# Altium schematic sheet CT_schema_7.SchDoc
size 274 x 160 mm
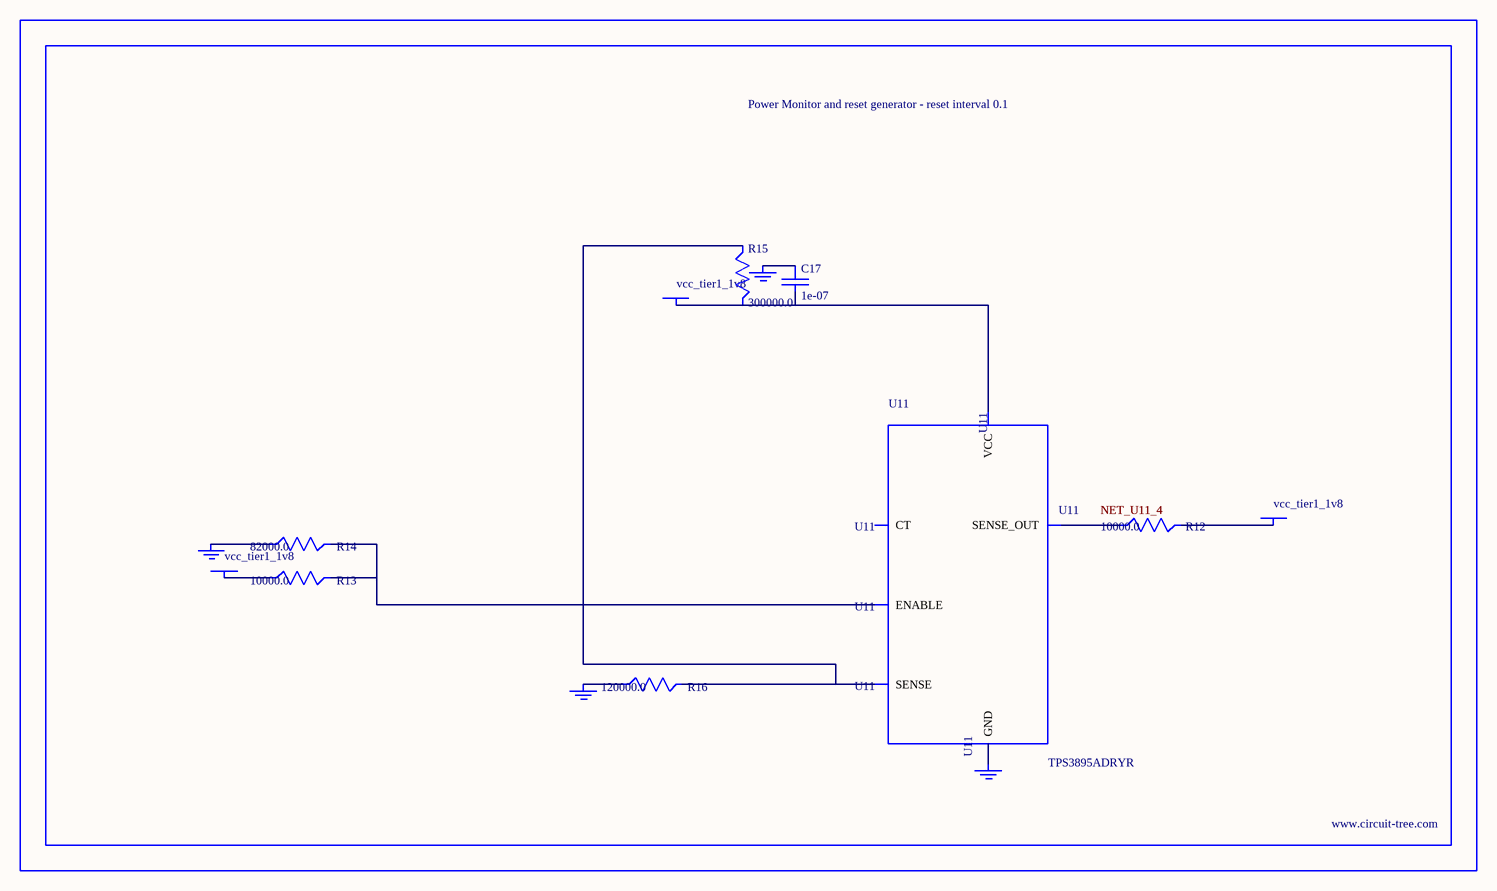
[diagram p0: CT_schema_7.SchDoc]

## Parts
BORDER6  (no value)
C17  1e-07  [C0402]
GND_INSTANCE_6_0  (no value)
GND_INSTANCE_6_1  (no value)
GND_INSTANCE_6_2  (no value)
GND_INSTANCE_6_3  (no value)
POWER_INSTANCE_6_0  vcc_tier1_1v8
POWER_INSTANCE_6_1  vcc_tier1_1v8
POWER_INSTANCE_6_2  vcc_tier1_1v8
R12  10000.0  [R0603]
R13  10000.0  [R0603]
R14  82000.0  [R0603]
R15  300000.0  [R0603]
R16  120000.0  [R0603]
U11  TPS3895ADRYR  [SON-6]

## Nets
NetC17_1: C17.1 GND_INSTANCE_6_2.0(GND)
NetC17_2: C17.2 POWER_INSTANCE_6_2.0(PWR) R15.2 U11.6(VCC)
NetGND_INSTANCE_6_0_0: GND_INSTANCE_6_0.0(GND) R14.1
NetGND_INSTANCE_6_1_0: GND_INSTANCE_6_1.0(GND) R16.1
NetGND_INSTANCE_6_3_0: GND_INSTANCE_6_3.0(GND) U11.2(GND)
NetPOWER_INSTANCE_6_0_0: POWER_INSTANCE_6_0.0(PWR) R13.1
NetPOWER_INSTANCE_6_1_0: POWER_INSTANCE_6_1.0(PWR) R12.2
NetR12_1: R12.1 U11.4(SENSE_OUT)
NetR13_2: R13.2 R14.2 U11.1(ENABLE)
NetR15_1: R15.1 R16.2 U11.3(SENSE)

Not connected (* = marked no-connect by the designer): U11 5(CT)

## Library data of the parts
BORDER6 = BORDER_PAGE6
C17 = C0402C104K3RACTU
GND_INSTANCE_6_0-GND_INSTANCE_6_3 = GND
POWER_INSTANCE_6_0-POWER_INSTANCE_6_2 = PWR
R12 R13 = RC0603JR-0710KL
R14 = RC0603JR-0782KL
R15 = RC0603JR-07300KL
R16 = RC0603JR-07120KL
